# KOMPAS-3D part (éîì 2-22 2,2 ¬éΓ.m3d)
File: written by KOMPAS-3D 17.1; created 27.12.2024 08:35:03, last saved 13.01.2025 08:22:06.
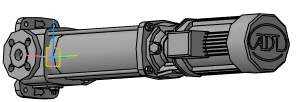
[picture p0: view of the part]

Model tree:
1. Операция без истории:4  (labels: ВМН 2-22 2,2 кВт)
